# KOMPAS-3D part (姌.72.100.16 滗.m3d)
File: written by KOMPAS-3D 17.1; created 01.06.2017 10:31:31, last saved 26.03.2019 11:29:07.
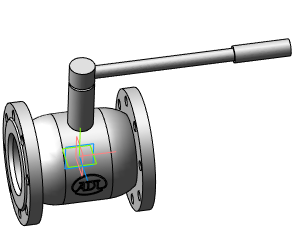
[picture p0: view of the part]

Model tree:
1. Операция без истории:2  (labels: Сталь 20  ГОСТ 1050-88)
